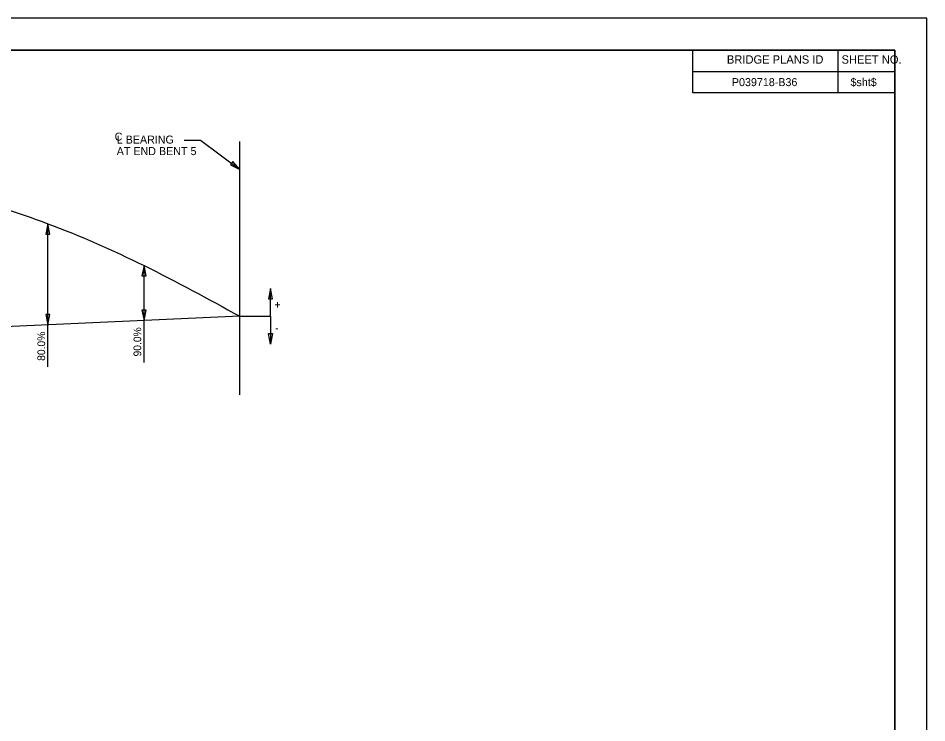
# Model space of a CAD drawing. Extents: x -125.5 to -89.4, y -5.1 to 16.9.
# Drawn here: x -103.72 to -89.53, y 5.93 to 16.93 of the extents above; entities that cross this region are included whole.
import ezdxf

# ---------------------------------------------------------------- set-up
doc = ezdxf.new("R2010")
doc.units = 0
for name, color, linetype in [('BR_AUTO DIMENSION', 7, 'Continuous'), ('BR_BORDER LINES', 7, 'Continuous'), ('BR_CENTER LINES', 7, 'Continuous'), ('BR_TABLE LINES', 7, 'Continuous'), ('BR_TEXT', 7, 'Continuous'), ('Level 31', 7, 'Continuous')]:
    doc.layers.add(name, color=color, linetype=linetype)

msp = doc.modelspace()

# ---------------------------------------------------------------- linework, layer by layer
at = {"layer": 'BR_AUTO DIMENSION'}
for p, q in [((-101.124, 15.029), (-100.87, 15.029)), ((-100.87, 15.029), (-100.257, 14.57)), ((-100.257, 12.28), (-99.777, 12.28))]:
    msp.add_line(p, q, dxfattribs=at)
for points in [[(-100.405, 14.644), (-100.257, 14.57), (-100.367, 14.694)], [(-103.222, 13.562), (-103.253, 13.725), (-103.285, 13.562)], [(-101.722, 12.91), (-101.753, 13.072), (-101.785, 12.91)], [(-99.746, 12.551), (-99.777, 12.713), (-99.809, 12.551)], [(-101.785, 12.375), (-101.753, 12.212), (-101.722, 12.375)], [(-103.285, 12.307), (-103.253, 12.145), (-103.222, 12.307)], [(-99.746, 12.009), (-99.777, 11.846), (-99.809, 12.009)]]:
    msp.add_lwpolyline(points, close=True, dxfattribs=at)
at = {"layer": 'BR_BORDER LINES'}
for p, q in [((-90.033, 16.434), (-123.699, 16.434)), ((-93.186, 15.767), (-93.186, 16.434)), ((-90.919, 15.767), (-90.919, 16.434)), ((-90.033, -4.566), (-90.033, 16.434)), ((-93.186, 16.104), (-90.033, 16.104)), ((-90.919, 16.104), (-90.033, 16.104)), ((-90.033, 15.767), (-93.186, 15.767))]:
    msp.add_line(p, q, dxfattribs=at)
at = {"layer": 'BR_CENTER LINES'}
msp.add_line((-100.257, 11.055), (-100.257, 15.009), dxfattribs=at)
at = {"layer": 'BR_TABLE LINES'}
for p, q in [((-103.253, 11.493), (-103.253, 13.725)), ((-101.753, 11.561), (-101.753, 13.072)), ((-99.777, 12.28), (-99.777, 12.713)), ((-100.257, 12.28), (-115.253, 11.605)), ((-99.777, 12.28), (-99.777, 11.846))]:
    msp.add_line(p, q, dxfattribs=at)
msp.add_lwpolyline([(-123.699, 16.434), (-90.033, 16.434), (-90.033, -4.566), (-123.699, -4.566)], close=True, dxfattribs=at)
msp.add_spline([(-115.253, 11.605), (-113.753, 12.522), (-112.253, 13.31), (-110.753, 13.927), (-109.253, 14.335), (-107.753, 14.512), (-106.253, 14.47), (-104.753, 14.197), (-103.253, 13.725), (-101.753, 13.072), (-100.257, 12.28)], degree=3, dxfattribs=at)
at = {"layer": 'Level 31'}
msp.add_lwpolyline([(-125.533, -5.066), (-89.533, -5.066), (-89.533, 16.934), (-125.533, 16.934)], close=True, dxfattribs=at)

# ---------------------------------------------------------------- texts
at = {"layer": 'BR_AUTO DIMENSION'}
for s, p in [('C', (-102.211, 15.022)), ('L BEARING', (-102.179, 14.976)), ('AT END BENT 5', (-102.179, 14.796))]:
    msp.add_text(s, height=0.125, dxfattribs=at).set_placement(p)
at = {"layer": 'BR_TEXT'}
for s, height, p in [('BRIDGE PLANS ID', 0.13, (-92.654, 16.224)), ('SHEET NO.', 0.13, (-90.864, 16.224)), ('P039718-B36', 0.125, (-92.576, 15.873)), ('$sht$', 0.125, (-90.724, 15.873)), ('-', 0.12, (-99.706, 12.039))]:
    msp.add_text(s, height=height, dxfattribs=at).set_placement(p)
for s, rotation, p in [('+', 360, (-99.716, 12.401)), ('90.0%', 90, (-101.797, 11.653)), ('80.0%', 90, (-103.297, 11.585))]:
    msp.add_text(s, height=0.12, rotation=rotation, dxfattribs=at).set_placement(p)

doc.saveas('drawing.dxf')
